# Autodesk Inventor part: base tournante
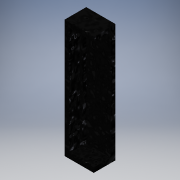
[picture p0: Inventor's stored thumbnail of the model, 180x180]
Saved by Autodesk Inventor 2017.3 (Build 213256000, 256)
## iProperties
Part Number: base tournante
Material: Plastique ABS
Document SubType Name: Modeling
Designer: ficho
Density: 1.06 g/cm^3
Appearance: Noir
Author: ficho
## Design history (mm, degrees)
sketch "Esquisse1"
  geometry: L1 (20, 17)-(0, 7) reference; L2 (0, 0)-(0, 7) reference; L3 (0, 0)-(25, 0) reference; L4 (25, 0)-(25, 17) reference; L5 (20, 17)-(25, 17) reference; L6 (25, 0)-(-6, 0); L7 (-6, 0)-(-6, 23); L8 (-6, 23)-(25, 23); L9 (25, 23)-(25, 0); C1 r 1 at (20, 5) reference; C2 r 0.75 at (4, 5) reference
  constraints: 8 end point, 2 parallel, 1 horizontal, 1 perpendicular
  dimensions: "d0" = 31 distance between parallel lines of L7 L4; "d1" = 23 distance between parallel lines of L8 L3
extrude "Extrusion1" new body sketch "Esquisse1" distance "d2" = 5; taper "d3" = 0 deg
sketch "Esquisse2"
  geometry: L1 (6, 0)-(-25, 0) reference; L2 (-25, 23)-(6, 23) reference; L3 (6, 0)-(1, 0); L4 (1, 0)-(1, 18); L5 (1, 23)-(6, 23); L6 (6, 23)-(6, 0); L7 (-25, 23)-(1, 23); L8 (1, 18)-(-25, 18); L9 (-25, 18)-(-25, 23); 1 further point
  constraints: 14 end point, 3 parallel, 2 horizontal, 1 perpendicular, 1 point on line
  dimensions: "d4" = 5 distance of L5.start L5.end; "d5" = 5 distance of L4.end L7.end
node "Plan de construction1"
extrude "Extrusion2" join sketch "Esquisse2" stored distance "d6" = 5; taper "d7" = 0 deg
sketch "Esquisse3"
  geometry: L1 (26, -23)-(26, -5) reference; L2 (31, -23)-(26, -23) reference; L3 (31, 0)-(31, -23) reference; L4 (0, 0)-(31, 0) reference; L5 (0, -5)-(0, 0) reference; L6 (26, -5)-(0, -5) reference; 1 further point
extrude "Extrusion3" join sketch "Esquisse3" distance "d8" = 1; taper "d9" = 0 deg
sketch "Esquisse4"
  geometry: L1 (0, -5)-(0, -23) reference; L2 (31, 0)-(0, 0); L3 (0, 0)-(0, -23); L4 (0, -23)-(31, -23); L5 (31, -23)-(31, 0); 2 further points
  constraints: 8 end point, 2 parallel, 1 coincident, 1 horizontal, 1 perpendicular
extrude "Extrusion4" join sketch "Esquisse4" distance "d10" = 5; taper "d11" = 0 deg
sketch "Esquisse5"
  geometry: L1 (-115, 10.75)-(-10, 10.75); L2 (-10, 10.75)-(-10, 14.25); L3 (-10, 14.25)-(-115, 14.25); L4 (-115, 14.25)-(-115, 10.75); L5 (-125, 0)-(-125, 23) reference; L6 (0, 23)-(0, 0) reference; L7 (0, 0)-(-125, 0) reference; 1 further point
  constraints: 8 end point, 2 parallel, 1 horizontal, 1 perpendicular
  dimensions: "d12" = 3.5 distance between parallel lines of L3 L1; "d13" = 10 distance between parallel lines of L5 L4; "d14" = 10 distance between parallel lines of L6 L2; "d15" = 10.75 distance between parallel lines of L7 L1
extrude "Extrusion5" cut sketch "Esquisse5" stored distance "d16" = 5; taper "d17" = 0 deg
sketch "Esquisse6"
  geometry: L1 (0, -5)-(0, -110) reference; L2 (0, -107.5)-(5, -107.5); L3 (10, -102.5)-(10, -12.5); L4 (5, -7.5)-(0, -7.5); L5 (0, -7.5)-(0, -107.5); L6 (-5, 5)-(26, 5) reference; L7 (26, -120)-(-5, -120) reference; A1 r 5 centre (5, -102.5) between (5, -107.5) and (10, -102.5); A2 r 5 centre (5, -12.5) between (10, -12.5) and (5, -7.5); 1 further point
  constraints: 8 end point, 4 point on circle, 4 tangent, 2 centre point, 2 parallel, 1 equal radius, 1 horizontal, 1 perpendicular, 1 point on line
  dimensions: "d18" = 10 distance between parallel lines of L3 L1; "d19" = 100 distance between parallel lines of L4 L2; "d20" = 12.5 distance between parallel lines of L4 L6; "d21" = 12.5 distance between parallel lines of L7 L2 (derived); "d22" = 5 radius of A1
node "Plan de construction2"
extrude "Extrusion6" join sketch "Esquisse6" stored distance "d23" = 5; taper "d24" = 0 deg
sketch "Esquisse7"
  geometry: C1 r 1.25 at (12.5, 97.5) reference; C2 r 1.25 at (12.5, 8.5) reference; 1 further point
hole "Perçage1" sketch "Esquisse7" at (12.5, 8.5), (12.5, 97.5) diameter "d25" = 1.5; stored, may be unused: countersink angle "d29" = 90 deg, drill point angle "d31" = 118 deg; dims "d26" = 6, "d27" = 4, "d28" = 2, "d30" = 5
fillet "Congé1" dims "d32" = 5
sketch "Esquisse8"
  geometry: C1 r 1 at (20, 5); A1 r 5 centre (20, 5) between (20, 0) and (25, 5) reference; 1 further point
  constraints: 1 centre point, 1 coincident
  dimensions: "d33" = 2 diameter of C1
hole "Perçage2" sketch "Esquisse8" at (20, 5) diameter "d34" = 2; stored, may be unused: countersink angle "d38" = 90 deg, drill point angle "d40" = 118 deg; dims "d35" = 6, "d36" = 4, "d37" = 2, "d39" = 5
sketch "Esquisse9"
  geometry: L1 (-6, 0)-(20, 0) reference; L2 (-6, 23)-(-6, 0) reference; C1 r 1.635 at (4, 5); 1 further point
  constraints: 1 centre point
  dimensions: "d48" = 5 distance from line of C1.centre L1; "d49" = 10 distance from line of C1.centre L2
hole "Perçage3" sketch "Esquisse9" at (4, 5) diameter "d41" = 2; stored, may be unused: countersink angle "d45" = 90 deg, drill point angle "d47" = 118 deg; dims "d42" = 6, "d43" = 4, "d44" = 2, "d46" = 5
node "Solide1"
node "Référence1"
node "Boucle projetée1"
node "Référence2"
node "Référence3"
